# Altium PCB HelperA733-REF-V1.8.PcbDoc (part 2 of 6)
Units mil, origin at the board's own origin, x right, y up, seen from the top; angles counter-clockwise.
Board outline 5905.51 x 4133.86 mil, 2 copper layers (Top, Bottom), stack 12.7 mil thick; 475 components, 355 nets, 1867 pads, 1471 vias.
Unrouted connection lines stored in the file: 1178.
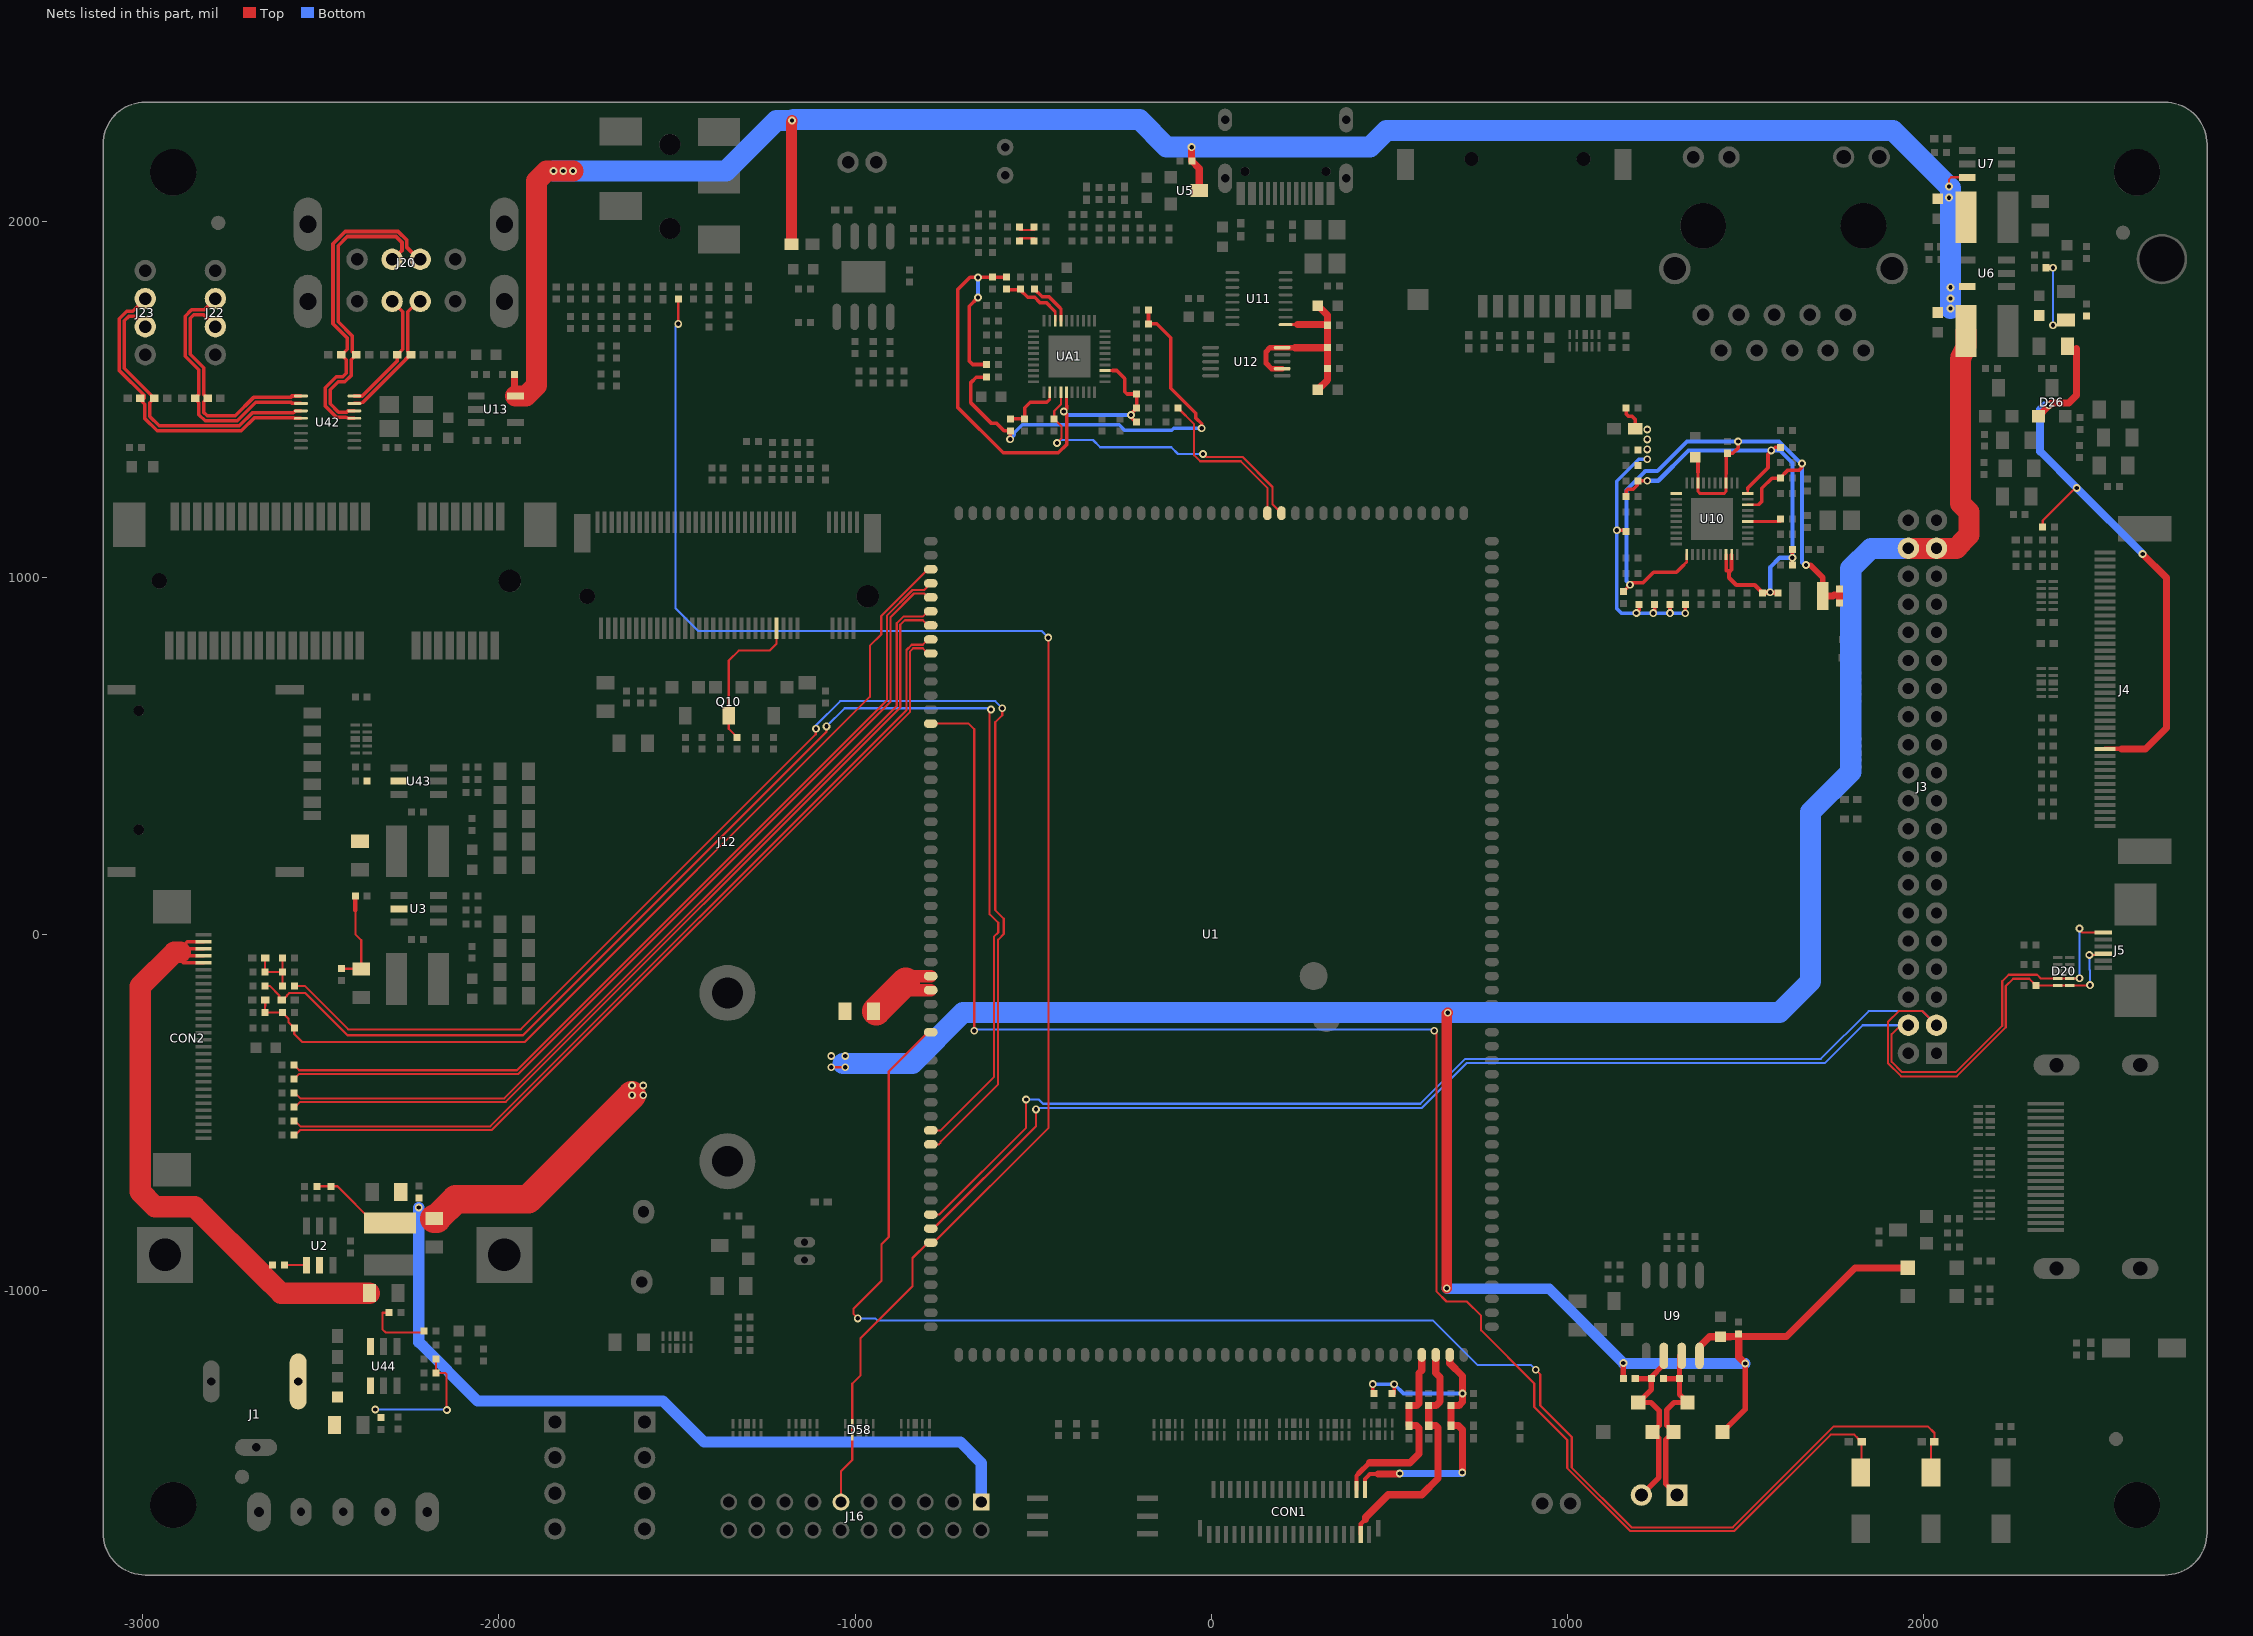
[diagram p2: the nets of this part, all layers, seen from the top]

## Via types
v1: diameter 22, hole 12, Top to Bottom, 1469 vias
v2: diameter 39.37, hole 35.43, Top to Bottom, 2 vias

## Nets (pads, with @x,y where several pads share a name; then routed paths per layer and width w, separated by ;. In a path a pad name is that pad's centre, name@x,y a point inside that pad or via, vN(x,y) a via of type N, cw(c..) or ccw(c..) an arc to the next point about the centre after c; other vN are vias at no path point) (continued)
5V: C4.1 C5.1 C6.1 C7.1 C19.2 C38.1 C44.1 C59.1 C60.1 CU1.2 D52.2 D69.1 FB1.2 J3.37 J3.38 J16.1 L1.2 L4.1 L5.1 R3.1 R4.1 R70.1 U5.3 U6.5 U7.6 U9.8 U13.5 | length 17018.4
  Top w6: R4.1@-2510.43,-708.06 C4.1@-2471.06,-708.06 -2452.36,-708.06 -2349.02,-811.4 L1.2@-2305.71,-811.4 ; -1955.71,1541.83 -1952.76,1538.88 U13.5@-1952.76,1509.84 ; v1(-1066.93,-374.02) v1(-1027.56,-374.02) ; v1(2070.87,2098.43) 2070.87,2118.11 2076.77,2124.02 U7.6@2122.05,2124.02
  Top w10: L4.1@2118.11,1692.91 L4.1@2129.9,1692.91
  Top w11.81: C19.2@-55.12,2169.29 C19.2@-54.13,2169.29
  Top w15: R70.1@1156.5,-1248.03 1156.5,-1241.5 v1(1156.58,-1204.06) ; D52.2@1435.14,-1397.64 1498.53,-1334.25 v1(1498.53,-1205.5)
  Top w19.68: CU1.2@-1955.71,1570.87 -1955.71,1541.83 -1955.71,1512.8 U13.5@-1952.76,1509.84 ; C19.2@-55.12,2169.29 v1(-55.12,2208.66) ; C19.2@-54.13,2169.29 -33.8,2148.96 U5.3@-33.8,2086.61
  Top w20: U9.8@1370.28,-1183.87 1370.28,-1158.4 1398.36,-1130.32 C59.1@1429.13,-1130.32 1456.69,-1130.32 1457.09,-1129.92 C60.1@1473.42,-1129.92 ; C60.1@1473.03,-1130.32 C60.1@1473.42,-1129.92 ; C60.1@1480.32,-1123.03 C60.1@1473.42,-1129.92 ; v1(1498.53,-1205.5) 1480.32,-1187.29 C60.1@1480.32,-1129.92 ; D69.1@1954.62,-937.01 1807.09,-937.01 1614.17,-1129.92 C60.1@1480.32,-1129.92 ; C60.1@1473.42,-1129.92 C60.1@1480.32,-1129.92
  Top w30: v1(660.83,-994.5) 660.83,-223.57 v1(663.61,-220.79)
  Top w31.5: FB1.2@-1178.17,1936.01 -1178.17,2278.53 -1177.17,2279.53 v1(-1177.17,2283.46)
  Top w59.06: U13.5@-1952.76,1509.84 -1923.64,1509.84 -1893.7,1539.78 -1893.7,2114.17 -1866.14,2141.73 v1(-1846.46,2141.73) v1(-1818.9,2141.73) v1(-1791.34,2141.73) ; J3.38@1956.69,1082.68 J3.37@2035.43,1082.68 2090.94,1082.68 2105.61,1097.34 2105.61,1098.94 2126.34,1119.67 2126.34,1184.68 2102.36,1208.66 2102.36,1614.17 2118.11,1649.61 L4.1@2118.11,1692.91
  Top w80: C5.1@-2181.1,-798.58 -2174.6,-798.58 -2120.11,-744.09 -1917.32,-744.09 v1(-1625.98,-452.76)
  Bottom w6: v1(-1066.93,-342.52) v1(-1027.56,-374.02) -1027.56,-363.19 v1(-1027.56,-342.52) ; v1(2070.87,2066.93) v1(2070.87,2098.43) ; v1(2074.8,1783.46) 2078.74,1787.4 2082.68,1787.4 2082.68,1814.96 v1(2074.8,1814.96)
  Bottom w30: v1(660.83,-994.5) 662.39,-996.06 948.58,-996.06 v1(1156.58,-1204.06) 1156.58,-1205.5 v1(1498.53,-1205.5)
  Bottom w31.5: v1(-2224.41,-767.72) -2224.41,-1145.67 -2059.06,-1311.02 -1539.37,-1311.02 -1424.19,-1426.2 -704.49,-1426.2 -645.67,-1485.02 J16.1@-645.67,-1594.49
  Bottom w59.06: v1(-1846.46,2141.73) v1(-1818.9,2141.73) v1(-1791.34,2141.73) -1362.2,2141.73 -1220.47,2283.46 v1(-1177.17,2283.46) -1173.23,2285.63 -202.13,2285.63 -125.16,2208.66 v1(-55.12,2208.66) 444.88,2208.66 492.13,2255.91 1913.39,2255.91 v1(2070.87,2098.43) 2074.8,2094.49 v1(2074.8,1814.96) v1(2074.8,1783.46) v1(2074.8,1755.91) ; -1033.46,-363.19 -1027.56,-363.19 -838.58,-363.19 -696.85,-220.79 v1(663.61,-220.79) 1594.49,-220.79 1681.59,-133.69 1681.59,341.87 1794.82,455.1 1794.82,1025.32 1852.18,1082.68 1909.45,1082.68 J3.38@1956.69,1082.68 J3.37@2035.43,1082.68
  other v1: -1594.49,-452.76 -1625.98,-425.2 -1594.49,-425.2
5V-IN: R3.2 U1.163 U1.164 | length 298
  Top w35: U1.164@-787.4,-157.48 -858.27,-157.48 -858.27,-133.86 -858.27,-118.11 U1.163@-787.4,-118.11
  Top w80: R3.2@-940.94,-216.54 -858.27,-133.86
12V-IN: C322.2 C324.1 J1.1 R157.1 R159.1 R238.2 U44.4 | length 373.3
  Top w6: R157.1@-2176.18,-1192.91 R238.2@-2176.18,-1232.28 -2150.04,-1232.28 -2147.13,-1235.2 -2147.13,-1335.9 v1(-2145.62,-1335.95)
  Bottom w6: v1(-2346.46,-1334.65) -2148.08,-1334.65 -2147.13,-1335.9 v1(-2145.62,-1335.95)
340_3V3: C67.1 C68.1 C69.1 C70.1 C71.1 U11.9 U12.7 U12.10 | length 641.8
  Top w8: U11.9@208.66,1710.43 241.46,1710.43
  Top w15: U12.7@198.82,1586.61 169.29,1586.61 153.54,1602.36 153.54,1633.86 165.35,1645.67 173.23,1645.67 U12.10@198.82,1645.67 235.43,1645.67
  Top w20: 235.43,1645.67 C69.1@325.79,1645.67 ; 241.46,1710.43 324.02,1710.43 C67.1@325.79,1708.66 ; C71.1@296.33,1525.07 298.82,1525.07 C71.1@298.82,1527.56 325.79,1554.53 C70.1@325.79,1586.61 C69.1@325.79,1645.67 ; C68.1@298.82,1763.78 325.79,1736.81 C67.1@325.79,1708.66 ; C69.1@325.79,1645.67 C67.1@325.79,1708.66
485_1+: D53.1 D54.2 J13.2 R70.2 R73.2 U9.6 | length 550.3
  Top w15: R70.2@1189.96,-1248.03 R73.2@1235.24,-1248.03 ; J13.2@1207.09,-1574.8 1256.38,-1525.51 1256.38,-1415.72 D54.2@1238.29,-1397.64 1256.9,-1379.03 1256.9,-1337.88 1233.98,-1314.96 D53.1@1198.72,-1314.96 1235.24,-1278.44 R73.2@1235.24,-1248.03 ; U9.6@1270.28,-1183.87 1270.28,-1207.68 1232.33,-1245.62 1235.48,-1247.65 1236.07,-1248.03 R73.2@1235.24,-1248.03
485_1-: D52.1 D53.2 J13.1 R73.1 R76.2 U9.7 | length 528.3
  Top w15: R73.1@1268.7,-1248.03 R76.2@1313.98,-1248.03 ; J13.1@1307.09,-1574.8 1275.59,-1543.31 1275.59,-1419.19 D52.1@1297.14,-1397.64 1277.94,-1378.43 1277.94,-1336.09 1299.07,-1314.96 D53.2@1336.72,-1314.96 1313.98,-1292.22 R76.2@1313.98,-1248.03 ; U9.7@1320.28,-1183.87 1313.98,-1183.87 R76.2@1313.98,-1248.03
AECRN: CA24.2 RA25.1 | length 57.1
  Top w6: CA24.2@-538.39,1944.88 -538.39,1952.76 -497.05,1952.76 RA25.1@-497.05,1944.88
AECRP: CA21.2 RA21.1 | length 57.1
  Top w6: CA21.2@-538.39,1984.25 -538.39,1976.38 -497.05,1976.38 RA21.1@-497.05,1984.25
AFVCC-CSI: CON1.36 CP1.1 D9.2 U1.34 | length 566.8
  Top w12: CON1.36@407.61,-1559.02 407.61,-1520.46 413.63,-1514.44
  Top w15: 413.63,-1514.44 444.04,-1484.03
  Top w20: 444.04,-1484.03 557.52,-1484.03 582.59,-1458.96 582.59,-1387.11 575.12,-1379.64 D9.2@555.12,-1379.64 CP1.1@555.12,-1323.82 575.83,-1323.82 582.68,-1316.97 582.68,-1232.28 590.55,-1224.41 590.55,-1209.7 U1.34@590.55,-1181.1
AGND/VRP: RA4.1 UA1.7 | length 130.2
  Top w8: -424.75,1757.55 -422.05,1754.85 UA1.7@-422.05,1721.48
  Top w10: RA4.1@-496.06,1810.04 -474.43,1788.41 -455.61,1788.41 -424.75,1757.55
AP-RESET: D40.2 K3.2 U1.167 | length 4509.4
  Top w6: v1(-992.13,-1078.74) -1003.94,-1066.93 -1003.94,-1051.18 -925.2,-972.44 -925.2,-870.08 -905.51,-850.39 -905.51,-385.83 -795.28,-275.59 U1.167@-787.4,-275.59 ; v1(910.5,-1223.14) 923.33,-1235.97 923.33,-1323.3 1011.81,-1411.78 1011.81,-1497.65 1179.51,-1665.35 1463.44,-1665.35 1746.91,-1381.89 2011.24,-1381.89 2029.81,-1400.46 D40.2@2029.81,-1425.2 2019.69,-1435.32 K3.2@2019.69,-1511.81
  Bottom w6: v1(-992.13,-1078.74) -942.91,-1078.74 -936.48,-1085.18 622.54,-1085.18 746.7,-1209.34 896.7,-1209.34 v1(910.5,-1223.14)
AVCC: D58.4 D58.7 J16.11 R61.1 U1.182 | length 4629.9
  Top w6: v1(-1496.06,1712.6) R61.1@-1496.06,1782.48 ; J16.11@-1039.37,-1594.49 -1039.37,-1507.87 -1007.88,-1476.38 D58.7@-1007.88,-1408.38 D58.4@-1007.88,-1374.3 -1007.88,-1262.15 -984.25,-1238.52 -984.25,-1133.86 -838.58,-988.19 -838.58,-909.45 -795.28,-866.14 -779.53,-866.14 -456.69,-543.31 -456.69,831.92 v1(-457.81,831.92)
  Bottom w6: v1(-1496.06,1712.6) -1503.94,1704.72 -1503.94,1228.88 -1503.83,1228.78 -1503.83,914 -1440.22,850.39 -476.28,850.39 v1(-457.81,831.92)
AVCC/VRA1: CA14.1 RA15.2 UA1.8 | length 188.9
  Top w8: -442.22,1751.08 -437.8,1746.66 UA1.8@-437.8,1721.48
  Top w10: RA15.2@-574.8,1810.04 -572.86,1808.1 -535.43,1808.1 -535.43,1807.22 -515.43,1787.22 -495.88,1787.22 -481.06,1772.41 -463.55,1772.41 -442.22,1751.08
AVDD: C39.1 C40.1 C41.1 D26.1 D31.2 J4.29 R30.1 R39.2 | length 1863.8
  Top w6: R30.1@2333.66,1141.73 2333.66,1160.43 2425.2,1251.97 v1(2429.13,1251.97) ; v1(2350.39,1484.25) v1@2352.88,1484.25
  Top w11.81: R39.2@2343.5,1870.08 v1(2362.2,1870.08)
  Top w12: J4.29@2507.87,519.68 2555.12,519.68
  Top w19.68: 2555.12,519.68 2622.05,519.68 2681.1,578.74 2681.1,1000 v1(2614.17,1066.93)
  Top w20: D26.1@2321.75,1453.13 2351.64,1483.01 2352.88,1484.25 2358.83,1490.2 2406.88,1490.2 2428.76,1512.08 2428.76,1642.75
  Bottom w6: v1(2362.2,1708.66) v1(2362.2,1870.08)
  Bottom w22.05: v1(2350.39,1484.25) 2338.58,1484.25 2326.31,1471.98 2326.31,1354.8 v1(2429.13,1251.97) v1(2614.17,1066.93)
AVDD10: CE1.2 CE2.2 CE3.2 CE4.2 CE5.2 CE6.2 L6.2 U10.3 U10.8 U10.21 U10.38 | length 2154.2
  Top w8: 1325.55,1035.49 1334.65,1044.59 U10.21@1334.65,1064.96 ; 1366.14,1296.19 1366.14,1241.9 1371.13,1236.91 1440.19,1236.91 1444.88,1241.6 U10.3@1444.88,1265.75 1444.88,1292.51 ; U10.38@1505.91,1204.72 1536.05,1204.72 1537.34,1206.01
  Top w10: CE2.2@1157.48,961.61 1181.65,985.79 1211.63,985.79 1241.37,1015.52 1305.58,1015.52 1325.55,1035.49 ; CE4.2@1358.27,1338.19 1366.14,1341.54 1366.14,1296.19 ; 1444.88,1292.51 1444.88,1345.47 CE5.2@1448.82,1349.41 1463.92,1349.41 1478.74,1364.23 v1(1478.74,1382.16) ; 1537.34,1206.01 1545.32,1213.99 1545.32,1250.85 1574,1279.53 CE1.2@1597.44,1279.53 1597.44,1280.42 1596.55,1280.42 1617.31,1301.18 1648.79,1301.18 1657.89,1310.28 v1(1657.89,1320.87)
  Top w15.75: v1(1669.29,1035.43) 1681.08,1035.43 1716.52,1000 L6.2@1716.52,948.82
  Top w19.68: L6.2@1716.52,948.82 1745.49,948.82 1747.79,951.12 1762.8,951.12 ; CE6.2@1762.8,929.13 1762.8,951.12 ; CE3.2@1762.8,968.5 1762.8,951.12
  Bottom w11.81: v1(1175.53,980.38) 1165.35,990.55 1165.35,1246.33 1218.24,1299.21 1251.97,1299.21 1334.91,1382.16 v1(1478.74,1382.16) 1593.59,1382.16 1656.38,1319.36 v1@1657.89,1317.86 ; v1(1657.89,1320.87) v1@1657.89,1317.86 ; v1(1669.29,1035.43) 1665.35,1035.43 1657.89,1042.9 v1@1657.89,1317.86
AVDD33: CE8.2 CE9.2 CE10.2 CE11.2 CE12.2 CE13.2 FB2.2 R84.1 R85.2 RE1.1 RE2.1 RE3.1 RE5.2 RE8.2 RE9.2 RE13.2 U10.11 U10.28 U10.29 U10.40 | length 2367.6
  Top w6: v1(1571.72,1357.58) v1@1572.88,1356.42
  Top w8: U10.40@1505.91,1236.22 1505.91,1247.85
  Top w10: v1(1138.39,1133.41) 1138.39,1133.89 1164.37,1133.89 RE3.1@1164.37,1129.92 ; RE2.1@1164.37,1228.35 1164.37,1243.95 1169.01,1248.59 1184.4,1248.59 1195.56,1259.75 CE8.2@1195.56,1275.71 ; R85.2@1164.37,1476.38 1164.37,1459.59 1170.81,1453.15 1181,1453.15 1189.98,1444.17 FB2.2@1189.98,1418.32 ; v1(1193.05,900.82) 1200.79,908.56 RE13.2@1200.79,924.21 ; CE8.2@1197.83,1271.65 1197.83,1272.18 v1(1223.6,1272.18) ; v1(1240.29,900.63) 1244.09,904.43 RE5.2@1244.09,924.21 ; RE8.2@1287.4,924.21 1287.56,924.21 v1(1287.56,900.66) ; v1(1330.34,900.33) 1330.34,924.21 RE9.2@1330.71,924.21 ; U10.28@1444.88,1064.96 1444.88,1051.18 1445.74,1050.32 1445.74,1019.68 1456.69,1019.68 1460.19,1023.18 U10.29@1460.19,1064.96 ; 1505.91,1247.85 1505.91,1251.78 1562.59,1308.46 1562.59,1346.13 1572.88,1356.42 1582.6,1366.14 CE9.2@1597.44,1366.14 ; RE1.1@1630.91,1035.43 1631.01,1035.43 v1(1631.01,1056.31) 1631.01,1078.74 R84.1@1630.91,1078.74
  Top w11.81: 1456.69,1019.68 1452.76,1015.75 1452.76,1000 1473.3,979.46 1525.46,979.46 CE10.2@1545.54,959.38 ; v1(1568.59,959.38) CE10.2@1545.54,959.38 ; CE12.2@1590.55,957.68 CE10.2@1547.24,957.68 CE10.2@1545.54,959.38
  Bottom w10: v1(1223.53,1332.38) 1199.74,1332.38 1137.8,1270.43 1137.8,1133.41 v1(1138.39,1133.41) 1137.8,1129.92 1137.8,913.52 1150.49,900.82 v1(1193.05,900.82) 1240.29,900.82 v1(1240.29,900.63) 1243.16,900.66 v1(1287.56,900.66) 1287.89,900.33 v1(1330.34,900.33)
  Bottom w11.81: v1(1223.6,1272.18) 1254.36,1272.18 1339.35,1357.17 v1@1564.33,1357.17 ; v1(1568.59,959.38) 1568.59,1029.22 1595.68,1056.31 v1(1631.01,1056.31) 1629.09,1058.22 1631.01,1060.14 1631.01,1321.98 1595.82,1357.17 v1@1564.33,1357.17 ; v1(1571.72,1357.58) 1564.74,1357.58 v1@1564.33,1357.17
  other v1: 1223.53,1360.38 1223.53,1388.38 1223.53,1416.38
AVDD-CSI: CON1.38 CP3.1 D11.2 R15.1 R16.1 U1.36 | length 1033.3
  Top w6: R16.1@507.24,-1290.13 R16.1@511.18,-1290.13
  Top w10: v1(453.39,-1263.39) 453.39,-1290.13 R15.1@456.06,-1290.13 ; R16.1@511.18,-1290.13 513.19,-1290.13 v1(513.19,-1263.54)
  Top w12: CON1.38@431.23,-1559.02 431.23,-1529.4 445.1,-1515.53 467.87,-1515.53
  Top w20: 467.87,-1515.53 527.74,-1515.53 v1(528.82,-1514.45) ; U1.36@669.29,-1181.1 669.29,-1204.72 704.98,-1240.41 v1(704.98,-1289.75) 704.98,-1313.99 695.15,-1323.82 CP3.1@673.23,-1323.82 D11.2@673.23,-1379.64 693.23,-1379.64 705.1,-1391.51 705.1,-1511.56 v1(704.56,-1511.56)
  Bottom w10: v1(453.39,-1263.39) 513.19,-1263.39 v1(513.19,-1263.54) 539.4,-1289.75 v1(704.98,-1289.75)
  Bottom w20: v1(528.82,-1514.45) 704.56,-1514.45 v1(704.56,-1511.56)
BL-PWMI: CL1.1 D18.2 R26.1 RL1.2 RL2.2 | length 169.5
  Top w6: D18.2@-2654.8,-68.37 -2655.73,-67.43 -2656.24,-66.93 -2656.5,-67.19 R26.1@-2656.5,-106.3 CL1.1@-2607.28,-106.3 ; RL1.2@-2607.28,-145.67 CL1.1@-2607.28,-106.3 ; RL2.2@-2607.28,-66.93 CL1.1@-2607.28,-106.3
CLKOUT-125M: RE12.2 U10.35 | length 99.4
  Top w8: U10.35@1505.91,1157.48 1597.44,1157.48 RE12.2@1597.44,1165.35
CLKREQN: J12.52 Q10.3 R230.2 | length 422.1
  Top w6: R230.2@-1330.71,552.16 -1354.33,575.79 Q10.3@-1354.33,612.54 -1354.33,767.72 -1326.77,795.28 -1240.16,795.28 -1220.47,814.96 J12.52@-1220.47,858.26
CODEC-AVCC: CA16.2 RA8.2 RA13.1 RA15.1 RA16.2 RA17.2 UA1.25 UA1.33 | length 1729.8
  Top w6: RA13.1@-211.8,1437.01 RA13.1@-209.65,1437.01
  Top w8: -406.3,1482.63 UA1.25@-406.3,1520.69 ; UA1.33@-298.04,1581.72 -276.29,1581.72
  Top w10: v1(-654.75,1786.77) -679.13,1762.38 -679.13,1608.33 -669.23,1598.43 RA8.2@-630.91,1598.43 ; RA15.1@-574.8,1843.5 RA16.2@-614.17,1843.5 -654.95,1843.5 v1(-654.95,1842.98) -661.63,1843.5 -677.17,1843.5 -711.53,1809.14 -711.53,1477.85 -584.35,1350.67 -429.22,1350.67 -406.3,1373.59 -406.3,1459.11 v1(-413.98,1466.79) -413.73,1466.79 -406.3,1474.22 -406.3,1482.63 ; -276.29,1581.72 -265.36,1581.72 -242.72,1559.08 -242.72,1522.27 -236.2,1515.75 CA16.2@-211.59,1515.75 ; RA13.1@-211.8,1437.01 -225.31,1450.52 v1(-225.31,1456.74) -225.31,1460.71 RA17.2@-209.65,1476.38 CA16.2@-209.65,1515.75 ; CA16.2@-210.3,1514.46 -210.62,1514.78 CA16.2@-211.59,1515.75 ; CA16.2@-205.71,1515.75 CA16.2@-209.65,1515.75 ; CA16.2@-211.59,1515.75 CA16.2@-209.65,1515.75
  Bottom w10: v1(-654.95,1842.98) -654.75,1842.78 v1(-654.75,1786.77) ; v1(-413.98,1466.79) -403.93,1456.74 v1(-225.31,1456.74)
CODEC-CPVDD: RA7.1 RA14.1 RA18.1 RA20.2 | length 1253.2
  Top w10: RA7.1@-630.91,1562.99 -659.7,1562.99 -674.58,1548.11 -674.58,1490.59 -617.06,1433.07 -602.36,1433.07 -581.69,1412.4 RA14.1@-564.65,1412.4 ; v1(-564.65,1388.8) RA14.1@-564.65,1412.4 ; RA14.1@-562.99,1412.4 RA14.1@-564.65,1412.4 ; RA18.1@-175.82,1715.96 -175.04,1714.61 RA18.1@-176.18,1712.6 -153.16,1712.6 -114.17,1673.61 -114.17,1532.29 -43.31,1461.42 -43.31,1448.15 -27.17,1432.01 v1(-27.17,1419.8)
  Top w11.81: RA18.1@-176.18,1712.6 RA20.2@-176.18,1751.97
  Bottom w10: v1(-564.65,1388.8) -552.63,1400.82 -552.63,1407.08 -530.58,1429.13 -258.21,1429.13 -242.46,1413.39 -112.19,1413.39 -105.78,1419.8 v1(-27.17,1419.8)
CODEC-IRQ: RA24.2 U1.108 UA1.24 | length 910.7
  Top w6: v1(-432.97,1378.44) -420.3,1391.11 -420.3,1425.23 RA24.2@-440.94,1445.87 -440.94,1468.19 -422.05,1487.08 UA1.24@-422.05,1520.69 ; v1(-23.26,1347.41) -14.99,1339.14 87.65,1339.14 171.94,1254.85 171.94,1206.01 U1.108@196.85,1181.1
  Bottom w6: v1(-432.97,1378.44) -424.95,1386.46 -332.17,1386.46 -312.07,1366.36 -112.53,1366.36 -93.58,1347.41 v1(-23.26,1347.41)
CODEC-RST: RA19.2 U1.109 | length 466.1
  Top w6: RA19.2@-93.5,1476.38 -48.15,1431.02 -48.15,1343.84 -31.45,1327.14 82.68,1327.14 157.48,1252.34 U1.109@157.48,1181.1
CPVDD: CA13.1 RA14.2 UA1.22 | length 170.6
  Top w8: -458.9,1495.35 -453.55,1500.7 UA1.22@-453.55,1520.69
  Top w10: RA14.2@-562.99,1445.87 CA13.1@-523.62,1445.87 -523.62,1477.33 -508.2,1492.75 -461.75,1492.75 -459.15,1495.35 -458.9,1495.35
CTP0-INT: D20.5 D20.6 J3.3 J5.4 R23.1 U1.180 | length 4314.2
  Top w6: U1.180@-787.4,-787.4 -779.53,-787.4 -775.71,-785.1 -774.33,-787.4 -763.78,-787.4 -519.68,-543.31 v1(-519.68,-464.57) ; J3.3@2035.43,-255.91 1996.06,-216.54 1929.13,-216.54 1899.45,-246.22 1899.45,-362.77 1936.28,-399.61 2092.23,-399.61 2230.02,-261.81 2230.02,-146.12 2250.56,-125.58 2295.9,-125.58 R23.1@2314.74,-144.43 D20.5@2375.45,-144.43 2466.36,-144.43 v1(2466.36,-143.56) ; v1(2464.57,-59.06) 2482.33,-58.02 2503.94,-58.02 J5.4@2503.94,-55.12
  Bottom w6: v1(-519.68,-464.57) -484.25,-464.57 -472.44,-476.38 586.61,-476.38 712.6,-350.39 1711.03,-350.39 1844.89,-216.54 1996.06,-216.54 J3.3@2035.43,-255.91 ; v1(2464.57,-59.06) 2464.57,-100.42 2466.36,-102.2 v1(2466.36,-143.56)
CTP0-RST: D20.4 D20.7 J3.4 J5.1 U1.181 | length 4100.5
  Top w6: U1.181@-787.4,-826.77 -779.53,-826.77 -492.13,-539.37 v1(-492.13,-492.13) ; J3.4@1956.69,-255.91 1935.04,-255.91 1909.45,-281.5 1909.45,-358.63 1938.61,-387.8 2089.89,-387.8 2220.02,-257.67 2220.02,-132.34 2238.19,-114.17 2317.86,-114.17 2328.43,-124.75 D20.4@2375.45,-124.75 2440.08,-124.75 2440.08,-124.51 v1(2436.85,-124.18) ; v1(2437.01,15.75) 2433.07,15.75 2444.88,3.94 J5.1@2503.94,3.94
  Bottom w6: v1(-492.13,-492.13) -488.19,-492.13 -484.25,-488.19 590.55,-488.19 716.54,-362.2 763.55,-362.2 763.78,-362.43 1721.5,-362.43 1828.02,-255.91 J3.4@1956.69,-255.91 ; v1(2436.85,-124.18) 2437.24,-123.79 2437.24,3.7 v1(2437.01,15.75)
DC_EN: R5.2 U2.4 | length 61.6
  Top w6: R5.2@-2601.38,-929.13 -2570.86,-929.13 -2570.48,-929.51 U2.4@-2539.96,-929.51
DCIN: C2.1 C3.1 C9.1 C10.1 C90.1 C91.1 CON2.26 CON2.27 CON2.28 CON2.29 R5.1 R233.1 R240.2 U2.5 U3.5 U43.5 U44.3 | length 2335.5
  Top w6: -2661.49,-957.5 -2635.39,-929.13 R5.1@-2634.84,-929.13 ; C10.1@-2440.94,-97.44 C9.1@-2386.18,-97.44 ; -2402.56,66.93 -2402.56,-0.77 -2385.83,-17.5 C9.1@-2385.83,-97.8 ; C3.1@-2308.07,-1062.99 -2326.77,-1062.99 -2326.77,-1109.25 -2317.91,-1118.11 -2208.66,-1118.11 -2204.72,-1114.17 R240.2@-2209.65,-1114.17
  Top w10: -2911.15,-51.65 -2900.84,-41.34 ; -2895.2,-51.65 -2885.83,-61.02 CON2.27@-2828.74,-61.02 ; -2893.7,-51.18 -2893.7,-41.34 ; CON2.26@-2828.74,-80.71 -2885.83,-80.71 -2900.84,-65.7 -2900.84,-51.65 -2900.84,-41.34 ; CON2.28@-2828.74,-41.34 -2893.7,-41.34 ; CON2.29@-2828.74,-21.65 -2874.02,-21.65 -2893.7,-41.34 ; -2900.84,-41.34 -2893.7,-41.34
  Top w11.81: -2402.56,66.93 R233.1@-2402.56,106.3
  Top w60: -2893.7,-51.18 -2893.7,-51.65 -2895.2,-51.65 -2900.84,-51.65 -2911.15,-51.65 -3006.47,-146.97 -3006.47,-723.57 -2964.79,-765.26 -2853.74,-765.26 -2662.35,-956.64 -2661.49,-957.5 -2611.12,-1007.87 C2.1@-2362.83,-1007.87
DM1: D78.1 J23.3 U42.3 | length 836.7
  Top w10: J23.3@-2992.13,1704.72 -3021.31,1733.91 -3037.95,1733.91 -3050.76,1721.09 -3050.76,1587.88 D78.1@-2966.82,1503.94 -2979.22,1491.54 -2979.22,1452.69 -2952.91,1426.38 -2728.29,1426.38 -2691.38,1463.29 -2576.27,1463.29 -2571.25,1468.31 U42.3@-2555.12,1468.31
DM2: D76.1 J22.3 U42.1 | length 676.9
  Top w10: J22.3@-2795.28,1704.72 -2828.52,1737.97 -2856.41,1737.97 -2865.83,1728.54 -2865.83,1627.32 -2827.65,1589.14 -2827.65,1514.37 D76.1@-2817.21,1503.94 -2827.65,1493.5 -2827.65,1463.79 -2818.23,1454.38 -2739.89,1454.38 -2688.18,1506.09 -2584.34,1506.09 -2580.39,1510.04 U42.1@-2555.12,1510.04
DM3: D65.1 J20.2 U42.15 | length 396.3
  Top w10: U42.15@-2405.51,1489.17 -2389.76,1489.17 -2380.83,1492.66 -2261.88,1611.61 -2261.88,1612.45 -2248.35,1625.98 D65.1@-2246.35,1625.98 -2255.8,1635.43 -2255.8,1746.56 -2220.47,1781.88 J20.2@-2220.47,1775.59
DM4: D67.1 J20.6 U42.13 | length 920.5
  Top w10: U42.13@-2405.51,1447.44 -2421.26,1447.44 -2430.2,1450.87 -2455.48,1450.87 -2486.71,1482.1 -2486.71,1533.32 -2455.86,1564.16 -2437.61,1564.16 -2428.26,1573.51 -2428.26,1611.61 D67.1@-2442.63,1625.98 -2440.63,1625.98 -2425.2,1641.42 -2425.2,1673.11 -2465.17,1713.09 -2465.17,1937.37 -2430.68,1971.87 -2282.61,1971.87 -2257.62,1946.88 -2257.62,1926.92 J20.6@-2220.47,1889.76
DP1: D79.1 J23.2 U42.4 | length 890.7
  Top w10: J23.2@-2992.13,1783.46 -3027.68,1747.91 -3043.75,1747.91 -3064.76,1726.89 -3064.76,1581.67 -2995.06,1511.96 -2995.06,1503.94 D79.1@-3005.62,1503.94 -3005.62,1500.8 -3006.76,1500.8 -2993.22,1487.27 -2993.22,1446.89 -2958.71,1412.38 -2722.49,1412.38 -2685.58,1449.29 -2575.99,1449.29 -2574.14,1447.44 U42.4@-2555.12,1447.44
DP2: D77.1 J22.2 U42.2 | length 722.2
  Top w10: J22.2@-2795.28,1783.46 -2826.77,1751.97 -2862.2,1751.97 -2879.83,1734.34 -2879.83,1621.52 -2841.65,1583.34 -2841.65,1514.37 D77.1@-2852.08,1503.94 -2852.08,1501.81 -2841.65,1491.38 -2841.65,1457.86 -2824.16,1440.38 -2734.09,1440.38 -2682.38,1492.09 -2582.72,1492.09 -2579.8,1489.17 U42.2@-2555.12,1489.17
DP3: D66.1 J20.3 U42.16 | length 347.1
  Top w10: U42.16@-2405.51,1510.04 -2383.25,1510.04 -2285.37,1607.92 -2285.37,1624.21 -2285.15,1624.21 D66.1@-2285.15,1625.98 -2269.8,1641.34 -2269.8,1746.17 J20.3@-2299.21,1775.59
DP4: D68.1 J20.7 U42.14 | length 842
  Top w10: U42.14@-2405.51,1468.31 -2423.47,1468.31 -2426.9,1464.87 -2449.68,1464.87 -2472.71,1487.9 -2472.71,1527.52 -2450.06,1550.16 -2431.81,1550.16 -2414.26,1567.72 -2414.26,1611.61 D68.1@-2399.89,1625.98 -2401.89,1625.98 -2410.79,1634.89 -2410.79,1678.51 -2450.78,1718.49 -2450.78,1931.97 -2424.88,1957.87 -2288.41,1957.87 -2271.62,1941.08 -2271.62,1918.07 J20.7@-2299.21,1893.7
DVDD-CSI: CON1.37 CP2.1 D10.2 U1.35 | length 700.9
  Top w12: CON1.37@419.42,-1685 419.42,-1656.23 433.04,-1642.61
  Top w20: 433.04,-1642.61 433.45,-1637.12 496.7,-1573.87 590.6,-1573.87 636.24,-1528.23 636.24,-1385.64 630.24,-1379.64 D10.2@610.24,-1379.64 CP2.1@610.24,-1323.82 630.54,-1323.82 641.72,-1312.64 641.72,-1243.92 629.92,-1232.12 629.92,-1203.18 U1.35@629.92,-1181.1
EDP-AUXN: C28.1 U1.135 | length 2498.7
  Top w6: C28.1@-2574.51,-367.86 -2559.83,-382.55 -1948.67,-382.55 -910.51,655.61 -910.51,893.6 -838.48,965.63 -806.02,965.63 U1.135@-787.4,984.25
EDP-AUXP: C25.1 U1.136 | length 2495.5
  Top w6: C25.1@-2574.51,-407.23 -2559.83,-392.54 -1944.53,-392.54 -900.51,651.47 -900.51,889.45 -834.34,955.63 -806.02,955.63 -795.28,944.88 U1.136@-787.4,944.88
EDP-EN: D17.2 R22.1 U1.174 | length 3799.9
  Top w6: R22.1@-2656.5,-145.67 -2642.9,-145.67 -2616.17,-172.4 -2616.17,-185.04 D17.2@-2608.55,-185.04 -2606.55,-185.04 -2593.99,-172.48 -2593.99,-171.75 -2587.59,-165.35 -2543.31,-165.35 -2424.66,-284 -1931.96,-284 -1079.98,567.98 v1(-1079.98,582.91) ; U1.174@-787.4,-551.18 -759.84,-551.18 -610.24,-401.57 -610.24,-7.87 -598.11,4.25 -598.11,31.5 -622.05,55.43 -622.05,622.05 -618.11,625.98 v1(-618.11,629.92)
  Bottom w6: v1(-1079.98,582.91) -1029.02,633.86 -618.11,633.86 v1(-618.11,629.92)
EDP-HPD: D15.2 R19.1 R20.2 R21.1 U1.134 | length 2618.6
  Top w6: D15.2@-2655.23,-185.04 -2655.23,-202.2 -2656.5,-203.47 R21.1@-2656.5,-220.47 R20.2@-2607.28,-220.47 -2590.55,-237.2 -2590.55,-247.05 R19.1@-2573.82,-263.78 -2573.82,-280.51 -2551.18,-303.15 -1927.23,-303.15 -958.31,665.77 -958.31,809.01 -926.5,840.83 -926.5,892.4 -795.28,1023.62 U1.134@-787.4,1023.62
EDP-PWM: RL1.1 U1.175 | length 3782.5
  Top w6: RL1.1@-2573.82,-145.67 -2544.45,-145.67 -2422.4,-267.72 -1938.25,-267.72 -1110.24,560.3 -1110.24,575.99 v1(-1109.79,575.99) ; U1.175@-787.4,-590.55 -764.72,-590.55 -759.84,-585.68 -759.84,-582.68 -598.43,-421.26 -598.43,-15.75 -582.68,0 -582.68,43.31 -606.3,66.93 -606.3,594.49 -586.61,614.17 v1(-586.61,633.86)
  Bottom w6: v1(-1109.79,575.99) -1109.79,585.12 -1041.37,653.54 -606.3,653.54 v1(-586.61,633.86)
EDP-TX0N: C23.1 U1.138 | length 2497.6
  Top w6: C23.1@-2574.51,-485.97 -2574.51,-487.49 -2572.99,-487.49 -2556.78,-471.28 -1979.96,-471.28 -872.95,635.72 -872.95,868.01 -860.13,880.83 -809.96,880.83 -795.28,866.14 U1.138@-787.4,866.14
EDP-TX0P: C24.1 U1.137 | length 2497.6
  Top w6: C24.1@-2574.51,-446.6 -2574.51,-445.08 -2572.99,-445.08 -2556.78,-461.29 -1984.1,-461.29 -882.95,639.87 -882.95,872.15 -864.28,890.83 -809.96,890.83 -795.28,905.51 U1.137@-787.4,905.51
EDP-TX1N: C21.1 U1.140 | length 2460.7
  Top w6: C21.1@-2574.51,-564.71 -2574.51,-566.23 -2572.99,-566.23 -2556.78,-550.03 -2019.33,-550.03 -845.39,623.91 -845.39,793.2 -836.51,802.09 -809.96,802.09 -795.28,787.4 U1.140@-787.4,787.4
EDP-TX1P: C22.1 U1.139 | length 2460.7
  Top w6: C22.1@-2574.51,-525.34 -2574.51,-523.82 -2572.99,-523.82 -2556.78,-540.03 -2023.47,-540.03 -855.39,628.06 -855.39,797.35 -840.65,812.09 -809.96,812.09 -795.28,826.77 U1.139@-787.4,826.77
FEL: D39.1 K1.1 U1.145 | length 4800.9
  Top w6: U1.145@-787.4,590.55 -681.1,590.55 -665.35,574.8 v1(-665.35,-271.65) ; v1(625.98,-271.65) 632.56,-278.23 632.56,-1003.71 660.22,-1031.37 716.76,-1031.37 757.28,-1071.89 757.28,-1112.4 906.46,-1261.57 906.46,-1327.45 999.09,-1420.08 999.09,-1499.08 1175.38,-1675.36 1468.58,-1675.36 1738.75,-1405.19 1805.08,-1405.19 1812.08,-1412.19 1820.76,-1425.2 D39.1@1825.09,-1425.2 1825.09,-1509.56 K1.1@1822.83,-1511.81
  Bottom w6: v1(-665.35,-271.65) -661.42,-267.72 625.98,-267.72 629.92,-271.65 v1(625.98,-271.65)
